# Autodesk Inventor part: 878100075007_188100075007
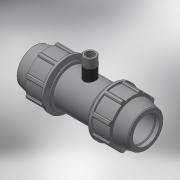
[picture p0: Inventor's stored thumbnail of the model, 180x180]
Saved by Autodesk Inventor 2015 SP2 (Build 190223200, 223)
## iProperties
Created: 2017-02
Part Number: 878100075007_188100075007
Material: Generic
Description: PLASSON COUPLER WITH RISER 75-3/4"
Document SubType Name: Modeling
Designer: KIM
Mass: 1772.99 g
Surface Area: 2354.31 cm^2
Volume: 1772.99 cm^3
Density: 1 g/cm^3
Appearance: Default
Author: KIM
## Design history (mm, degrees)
derived "87810.ipt"
feature "Solid1::87810.ipt"
feature "Solid2::87810.ipt"
tag "TaggingFeature1"
body "Solid1"
other parameters: "d2" = 75, "d4" = 13.5, "d5" = 38.88, "d7" = 132, "d11" = 5.4, "d13" = 120 deg, "d14" = 97.5, "d15" = 12 deg, "d16" = 114.84, "d18" = 3.75, "d19" = 35 deg, "d20" = 17.5 deg, "d21" = 122.76, "d23" = 0, "d25" = 360 deg, "d27" = 2.64, "d33" = 1.5, "d42" = 58.32, "d43" = 3.96, "d46" = 2.25, "d68" = 5.4, "d72" = 105, "d73" = 26.441, "d74" = 18, "d76" = 18.5087, "d77" = 21.6, "d80" = 0.79323, "d91" = 99, "d93" = 137, "d95" = 67.5, "d99" = 324, "d101" = 0, "d103" = 0, "d105" = 0, "d106" = 26.96982, "d107" = 6.48, "d108" = 0, "d_" = 75, "E_" = 132, "A_" = 105, "l_" = 137, "l_2" = 18, "H_" = 324, "R_" = 26.441
